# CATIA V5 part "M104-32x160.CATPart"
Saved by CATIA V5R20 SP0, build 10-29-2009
Part number: M104-32x160
Source: Unknown
Bounding box of the stored display mesh (mm): x -15.868 to 15.868, y -15.868 to 15.868, z 0 to 160
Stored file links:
  C:\Users\Utente\Desktop\IO LAVORO\3D X SITO CF\X SITO\M104\M104-32x160.CATPart

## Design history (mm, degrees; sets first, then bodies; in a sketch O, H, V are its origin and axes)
Body1 (main body)
  Solid1 "PartBody": solid without history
